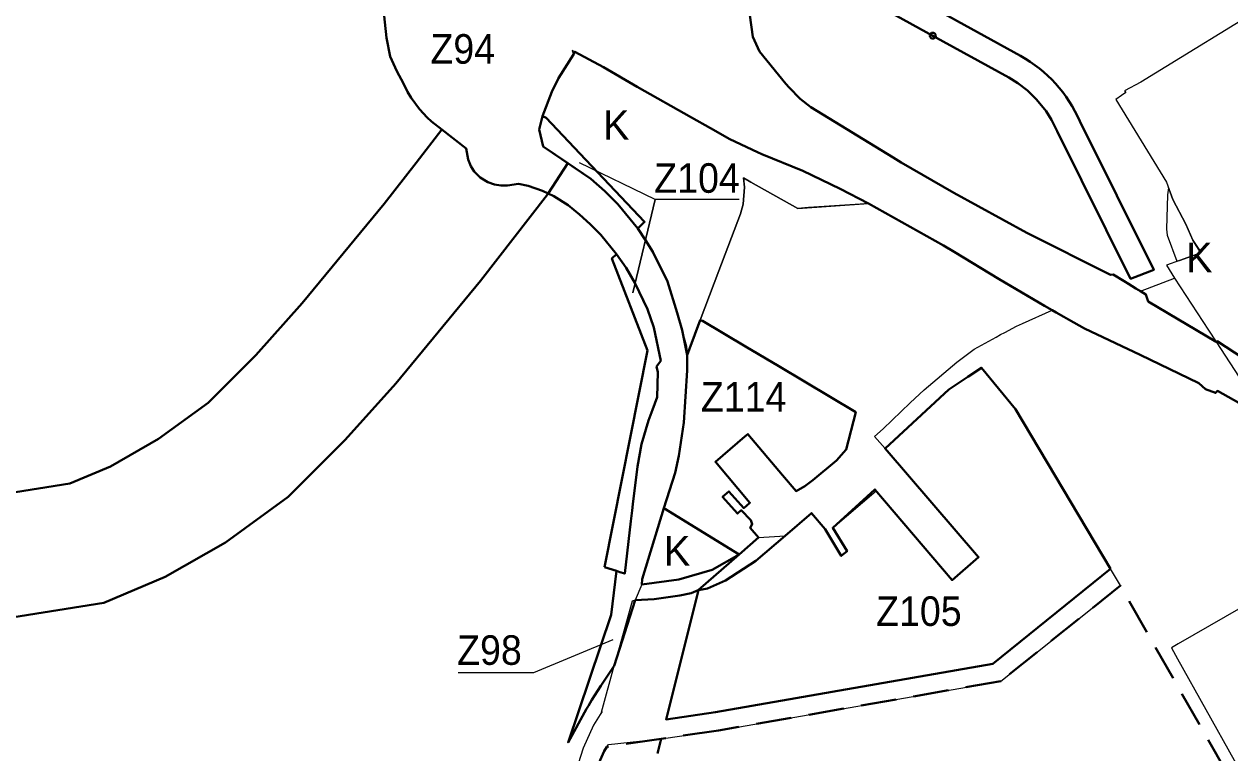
# Model space of a CAD drawing. Extents: x -650276 to -642489, y -1074425 to -1066658.
# Drawn here: x -647044 to -646064, y -1069196 to -1068604 of the extents above; entities that cross this region are included whole.
import ezdxf

# ---------------------------------------------------------------- set-up
doc = ezdxf.new("R2010")
doc.units = 0
doc.header["$LTSCALE"] = 9.6
doc.header["$PDMODE"] = 32
doc.header["$PDSIZE"] = 4.8
doc.linetypes.add('MEDIUM_DASHED', pattern=[4.5, 3, -1.5])
for name, color, linetype, lineweight in [('1', 7, 'Continuous', 13), ('43', 7, 'Continuous', 13), ('44', 7, 'Continuous', 40), ('45', 7, 'Continuous', 40), ('46', 7, 'Continuous', 13), ('47', 7, 'Continuous', 13), ('61', 7, 'MEDIUM_DASHED', 40)]:
    doc.layers.add(name, color=color, linetype=linetype, lineweight=lineweight)

msp = doc.modelspace()

# ---------------------------------------------------------------- linework, layer by layer
at = {"layer": '1'}
for points in [[(-646028.19, -1068584.65), (-646136.66, -1068651.17), (-646149.99, -1068658.12), (-646149.04, -1068659.6), (-646152.41, -1068662.01), (-646157.02, -1068665.31), (-646115.89, -1068732.3), (-646110.72, -1068746.41), (-646100.168, -1068766.374), (-646094.58, -1068779.42), (-646089.04, -1068787.68), (-646088.06, -1068789.6), (-646105.32, -1068795.84), (-646115.95, -1068799.69), (-646109.35, -1068810.23), (-646081.72, -1068852.51), (-646075.56, -1068861.95), (-646053.3, -1068896.01)], [(-646208.7, -1068836.39), (-646214.92, -1068832.85), (-646251.73, -1068811.04), (-646288.37, -1068789.04), (-646357.87, -1068749.64), (-646364.77, -1068750.16), (-646406.7, -1068753.03), (-646415.3, -1068753.62), (-646453.51, -1068732.3), (-646459.54, -1068728.94), (-646458.57, -1068736.31), (-646459.59, -1068750.19), (-646461.92, -1068757.93), (-646479.45, -1068804.37), (-646494.52, -1068844.29), (-646492.73, -1068845.01), (-646457.86, -1068865.8), (-646430.86, -1068881.89), (-646368.3, -1068919.19)], [(-646114.15, -1068737.05), (-646115.07, -1068742.74), (-646115.86, -1068770.5), (-646115.26, -1068775.39), (-646107.5, -1068796.63)], [(-646088.06, -1068789.6), (-646094.58, -1068779.42), (-646100.171, -1068766.368), (-646110.72, -1068746.41), (-646114.013, -1068737.422), (-646114.15, -1068737.05)], [(-646107.5, -1068796.63), (-646105.32, -1068795.84), (-646088.06, -1068789.6)], [(-646368.3, -1068919.19), (-646376.02, -1068949.34), (-646383.86, -1068958.24), (-646403.13, -1068974.41), (-646409.67, -1068979.3), (-646416.71, -1068983.21), (-646427.77, -1068970.39), (-646455.78, -1068936.87), (-646468.83, -1068948.26), (-646482.2, -1068959.52), (-646454.21, -1068992.73), (-646459.25, -1068996.98), (-646471.24, -1068983.41), (-646476.35, -1068987.98), (-646464.24, -1069001.49), (-646461.29, -1068998.81), (-646453.48, -1069006.75), (-646452.37, -1069010.01), (-646453.88, -1069013.1), (-646449.47, -1069018.25), (-646447.2, -1069020.9), (-646425.52, -1069019.41), (-646410.96, -1069006.99), (-646404.269, -1069001.033), (-646393.09, -1069014.234), (-646379.973, -1069035.889), (-646375.346, -1069032.07), (-646386.936, -1069012.936), (-646351.641, -1068983.083), (-646305.65, -1069037.39), (-646290.099, -1069055.423), (-646268.528, -1069036.82), (-646344.49, -1068948.736), (-646353.114, -1068938.868), (-646345.87, -1068932.56), (-646324.04, -1068911.62), (-646312.72, -1068901.07), (-646286.22, -1068878.44), (-646272.13, -1068867.84), (-646254.36, -1068858.21), (-646250.58, -1068856.16), (-646247.14, -1068854.3), (-646237.82, -1068849.24), (-646232.81, -1068847.24), (-646208.7, -1068836.39)], [(-645993.85, -1069042.59), (-646106.31, -1069107.25), (-646111.84, -1069110.389), (-646107, -1069119.41), (-646037.99, -1069242.88)]]:
    msp.add_lwpolyline(points, dxfattribs=at)
at = {"layer": '44'}
for points in [[(-646561.544, -1068464.842), (-646553.677, -1068472.283), (-646544.525, -1068479.79), (-646535.245, -1068486.342), (-646523.105, -1068493.54), (-646493.511, -1068509.855), (-646305.678, -1068613.404)], [(-646234.342, -1068629.893), (-646234.342, -1068629.892), (-646438.626, -1068517.274), (-646513.45, -1068476.025), (-646513.567, -1068475.963)], [(-646337.93, -1068712.4), (-646404.83, -1068671.52), (-646413.45, -1068664.71), (-646422.32, -1068655.58), (-646425.11, -1068652.37), (-646446.54, -1068626.14), (-646451.82, -1068614.31), (-646458.03, -1068569.26), (-646461.14, -1068556.34), (-646469.51, -1068538.15), (-646477.41, -1068526.45), (-646487.92, -1068516.87), (-646498.48, -1068511.26), (-646507.4, -1068508.45), (-646514.39, -1068507.56), (-646528.18, -1068507.58), (-646531.9, -1068509.25), (-646537.71, -1068508.16), (-646545.57, -1068511.42)], [(-646752.59, -1068584.55), (-646749.35, -1068615.18), (-646746.32, -1068630.23), (-646740.91, -1068642.34), (-646735.62, -1068652.21), (-646732.25, -1068659.06), (-646729.34, -1068663.94), (-646722.6, -1068673.11), (-646716.39, -1068679.8), (-646716.39, -1068679.8), (-646712.93, -1068683), (-646704.316, -1068689.698), (-646684.7, -1068704.95), (-646682.98, -1068714.07), (-646680.88, -1068719.28), (-646678.08, -1068723.7)], [(-646305.678, -1068613.404), (-646243.997, -1068647.407), (-646236.707, -1068651.891), (-646228.691, -1068658.051), (-646221.348, -1068665.144), (-646213.659, -1068674.696), (-646209.179, -1068681.795), (-646204.654, -1068690.937), (-646145.083, -1068810.83), (-646126.317, -1068803.654), (-646186.371, -1068682.825)], [(-646602.095, -1068716.98), (-646622.01, -1068703.3), (-646625.35, -1068689.7), (-646622.68, -1068678.75), (-646615.19, -1068659.11), (-646609.7, -1068647.84), (-646597.4, -1068628.74), (-646596.28, -1068626.52), (-646596.28, -1068626.52), (-646573.14, -1068638.98), (-646545.73, -1068654.81), (-646545.73, -1068654.81), (-646501.64, -1068679.81), (-646486.23, -1068688.54), (-646470.65, -1068697.38), (-646448.02, -1068707.99), (-646444.51, -1068709.64), (-646411.3, -1068723.11), (-646380.94, -1068737.81), (-646357.87, -1068749.64), (-646297.08, -1068783.8), (-646288.37, -1068789.04), (-646251.73, -1068811.04), (-646214.92, -1068832.85), (-646208.7, -1068836.39), (-646205.48, -1068838.23), (-646199.24, -1068841.79), (-646195.52, -1068843.92), (-646182.57, -1068851.3), (-646137.23, -1068872.6), (-646089.63, -1068895.5), (-646084.1, -1068900.51), (-646076.09, -1068903.48), (-646074.51, -1068901.9), (-646057.13, -1068911.62)], [(-646704.316, -1068689.698), (-646725.374, -1068716.786), (-646751.116, -1068749.975), (-646817.718, -1068830.545), (-646855.506, -1068872.883), (-646894.206, -1068911.595), (-646934.465, -1068940.759)], [(-646617.991, -1068741.504), (-646622.62, -1068739.32), (-646634.37, -1068735.27), (-646642.04, -1068733.74), (-646651.21, -1068734.99), (-646656.47, -1068735.13), (-646661.5, -1068734.35), (-646667.17, -1068732.38), (-646673.16, -1068728.69), (-646678.08, -1068723.7), (-646680.88, -1068719.28), (-646682.98, -1068714.07), (-646684.7, -1068704.95), (-646704.316, -1068689.698)], [(-646618.655, -1068742.359), (-646617.991, -1068741.504), (-646617.991, -1068741.503), (-646602.095, -1068716.98)], [(-646539.08, -1068779.481), (-646545.32, -1068769.89), (-646561.5, -1068750.22), (-646571.91, -1068739.54), (-646583.49, -1068729.76), (-646602.095, -1068716.98), (-646617.991, -1068741.503)], [(-646046.48, -1068879.92), (-646074.78, -1068861.51), (-646075.56, -1068861.95), (-646130.68, -1068829.21), (-646132.62, -1068823.54), (-646136.99, -1068820.88), (-646140.73, -1068818.61), (-646146.85, -1068814.88), (-646150.26, -1068812.81), (-646159.1, -1068807.43), (-646161.45, -1068807.54), (-646229.44, -1068773.53), (-646288.59, -1068740.88), (-646331.26, -1068716.25), (-646337.93, -1068712.4)], [(-647065.688, -1069087.73), (-646978.92, -1069073.93), (-646929.186, -1069052.925), (-646880.163, -1069024.903), (-646829.104, -1068987.917), (-646782.784, -1068941.581), (-646741.85, -1068895.719), (-646673.05, -1068812.491), (-646618.655, -1068742.359), (-646617.991, -1068741.504)], [(-646617.991, -1068741.503), (-646613.44, -1068743.65), (-646601.86, -1068751.01), (-646592.53, -1068758.66), (-646583.98, -1068766.42), (-646575.28, -1068775.04), (-646562.49, -1068790.69), (-646554.8, -1068801.98)], [(-646509.323, -1068852.529), (-646513.27, -1068838.37), (-646521.18, -1068812.95), (-646532.92, -1068788.95), (-646539.08, -1068779.481)], [(-646554.8, -1068801.98), (-646547.68, -1068814.22), (-646547.433, -1068814.73)], [(-646547.433, -1068814.73), (-646537.35, -1068835.56), (-646532.16, -1068850.47), (-646526.64, -1068877.47), (-646530.06, -1068882.16)], [(-646524, -1068997), (-646514.91, -1068968.48), (-646514.91, -1068968.48), (-646512.07, -1068954.68), (-646507.91, -1068927.47), (-646505.12, -1068885.31), (-646505.17, -1068872.78), (-646509.323, -1068852.529)], [(-646530.06, -1068882.16), (-646528.92, -1068886.55), (-646529.44, -1068906.81), (-646533.28, -1068917.17)], [(-646533.28, -1068917.17), (-646536.54, -1068925.95), (-646542.16, -1068945.12), (-646545.42, -1068963.3), (-646549.17, -1068993.71), (-646549.81, -1068998.88), (-646550.89, -1069007.7), (-646555.84, -1069050.22), (-646559.8, -1069048.98), (-646562.61, -1069048.08)], [(-646934.465, -1068940.759), (-646973.61, -1068963.135), (-647006.63, -1068977.08), (-647076.422, -1068988.18), (-647128.674, -1068991.167), (-647199.672, -1068994.255), (-647268.348, -1068994.255), (-647338.816, -1068991.19), (-647417.895, -1068984.986), (-647502.412, -1068977.157), (-647629.424, -1068964.608), (-647699.561, -1068956.635), (-647749.978, -1068953.416)], [(-646462.98, -1069034.61), (-646485, -1069047), (-646512, -1069055), (-646542, -1069059), (-646541.71, -1069054.76), (-646524, -1068997)], [(-646547.412, -1069071.71), (-646532, -1069071), (-646511, -1069068), (-646502, -1069066), (-646496.317, -1069063.61), (-646462.98, -1069034.61)], [(-646562.61, -1069048.08), (-646566.82, -1069083.62), (-646601.82, -1069187.25), (-646586.97, -1069160.06), (-646585.42, -1069157.56), (-646583.89, -1069155.1), (-646582.46, -1069152.81), (-646582.46, -1069152.81), (-646575.4, -1069141.46), (-646564.54, -1069125.08), (-646547.412, -1069071.71)]]:
    msp.add_lwpolyline(points, dxfattribs=at)
at = {"layer": '44', "lineweight": 13}
msp.add_lwpolyline([(-646691.216, -1069130.395), (-646629.734, -1069130.395), (-646565.156, -1069103.837)], dxfattribs=at)
msp.add_lwpolyline([(-646691.216, -1069130.395), (-646629.734, -1069130.395), (-646565.156, -1069103.837)], dxfattribs=at)
at = {"layer": '44'}
msp.add_arc((-646287.447, -1068726.224), 110, 23.23727, 61.13296, dxfattribs=at)
msp.add_point((-646305.678, -1068613.404), dxfattribs=at)
at = {"layer": '45'}
msp.add_line((-646583.49, -1068729.76), (-646571.91, -1068739.54), dxfattribs=at)
msp.add_line((-646583.49, -1068729.76), (-646571.91, -1068739.54), dxfattribs=at)
for points in [[(-646571.91, -1068739.54), (-646561.5, -1068750.22), (-646545.32, -1068769.89), (-646539.78, -1068764.65), (-646596.93, -1068704.15), (-646619.74, -1068680.15), (-646622.68, -1068678.75), (-646625.35, -1068689.7)], [(-646571.91, -1068739.54), (-646561.5, -1068750.22), (-646545.32, -1068769.89), (-646539.78, -1068764.65), (-646596.93, -1068704.15), (-646619.74, -1068680.15), (-646622.68, -1068678.75), (-646625.35, -1068689.7)], [(-646625.35, -1068689.7), (-646622.01, -1068703.3), (-646583.49, -1068729.76)], [(-646625.35, -1068689.7), (-646622.01, -1068703.3), (-646583.49, -1068729.76)], [(-646562.49, -1068790.69), (-646566.34, -1068794.32), (-646537.3, -1068868.95), (-646572.42, -1069044.94)], [(-646562.49, -1068790.69), (-646566.34, -1068794.32), (-646537.3, -1068868.95), (-646572.42, -1069044.94)], [(-646526.64, -1068877.47), (-646532.16, -1068850.47), (-646537.35, -1068835.56), (-646547.68, -1068814.22), (-646554.8, -1068801.98), (-646562.49, -1068790.69)], [(-646526.64, -1068877.47), (-646532.16, -1068850.47), (-646537.35, -1068835.56), (-646547.68, -1068814.22), (-646554.8, -1068801.98), (-646562.49, -1068790.69)], [(-646529.44, -1068906.81), (-646528.92, -1068886.55), (-646530.06, -1068882.16), (-646526.64, -1068877.47)], [(-646529.44, -1068906.81), (-646528.92, -1068886.55), (-646530.06, -1068882.16), (-646526.64, -1068877.47)], [(-646555.84, -1069050.22), (-646550.89, -1069007.7), (-646549.81, -1068998.88), (-646549.17, -1068993.71), (-646545.42, -1068963.3), (-646542.16, -1068945.12), (-646536.54, -1068925.95), (-646533.28, -1068917.17), (-646529.44, -1068906.81)], [(-646555.84, -1069050.22), (-646550.89, -1069007.7), (-646549.81, -1068998.88), (-646549.17, -1068993.71), (-646545.42, -1068963.3), (-646542.16, -1068945.12), (-646536.54, -1068925.95), (-646533.28, -1068917.17), (-646529.44, -1068906.81)], [(-646572.42, -1069044.94), (-646562.61, -1069048.08), (-646559.8, -1069048.98), (-646555.84, -1069050.22)], [(-646572.42, -1069044.94), (-646562.61, -1069048.08), (-646559.8, -1069048.98), (-646555.84, -1069050.22)]]:
    msp.add_lwpolyline(points, dxfattribs=at)
for points in [[(-646512.07, -1068954.68), (-646507.91, -1068927.47), (-646505.12, -1068885.31), (-646505.17, -1068872.78), (-646503.24, -1068867.61), (-646494.52, -1068844.29), (-646492.73, -1068845.01), (-646457.86, -1068865.8), (-646430.86, -1068881.89), (-646368.3, -1068919.19), (-646376.02, -1068949.34), (-646383.86, -1068958.24), (-646403.13, -1068974.41), (-646409.67, -1068979.3), (-646416.71, -1068983.21), (-646427.77, -1068970.39), (-646455.78, -1068936.87), (-646458.21, -1068938.99), (-646482.2, -1068959.52), (-646454.21, -1068992.73), (-646459.25, -1068996.98), (-646471.24, -1068983.41), (-646476.35, -1068987.98), (-646464.24, -1069001.49), (-646461.29, -1068998.81), (-646453.48, -1069006.75), (-646452.37, -1069010.01), (-646453.88, -1069013.1), (-646447.2, -1069020.9), (-646462.98, -1069034.61), (-646524, -1068997), (-646514.91, -1068968.48), (-646514.91, -1068968.48)], [(-646512.07, -1068954.68), (-646507.91, -1068927.47), (-646505.12, -1068885.31), (-646505.17, -1068872.78), (-646503.24, -1068867.61), (-646494.52, -1068844.29), (-646492.73, -1068845.01), (-646457.86, -1068865.8), (-646430.86, -1068881.89), (-646368.3, -1068919.19), (-646376.02, -1068949.34), (-646383.86, -1068958.24), (-646403.13, -1068974.41), (-646409.67, -1068979.3), (-646416.71, -1068983.21), (-646427.77, -1068970.39), (-646455.78, -1068936.87), (-646458.21, -1068938.99), (-646482.2, -1068959.52), (-646454.21, -1068992.73), (-646459.25, -1068996.98), (-646471.24, -1068983.41), (-646476.35, -1068987.98), (-646464.24, -1069001.49), (-646461.29, -1068998.81), (-646453.48, -1069006.75), (-646452.37, -1069010.01), (-646453.88, -1069013.1), (-646447.2, -1069020.9), (-646462.98, -1069034.61), (-646524, -1068997), (-646514.91, -1068968.48), (-646514.91, -1068968.48)], [(-646161.484, -1069046.228), (-646238.632, -1068916.799), (-646266.118, -1068883.048), (-646277.268, -1068890.446), (-646292.75, -1068900.72), (-646344.49, -1068948.736), (-646268.528, -1069036.82), (-646290.099, -1069055.423), (-646352.71, -1068981.82), (-646386.936, -1069012.936), (-646375.346, -1069032.07), (-646379.973, -1069035.889), (-646393.09, -1069014.234), (-646404.269, -1069001.033), (-646425.52, -1069019.41), (-646449.418, -1069039.804), (-646474.13, -1069055.83), (-646488.537, -1069062.169), (-646495.89, -1069063.531), (-646522.35, -1069168.648), (-646482.211, -1069162.813), (-646256.824, -1069123.414)], [(-646161.484, -1069046.228), (-646238.632, -1068916.799), (-646266.118, -1068883.048), (-646277.268, -1068890.446), (-646292.75, -1068900.72), (-646344.49, -1068948.736), (-646268.528, -1069036.82), (-646290.099, -1069055.423), (-646352.71, -1068981.82), (-646386.936, -1069012.936), (-646375.346, -1069032.07), (-646379.973, -1069035.889), (-646393.09, -1069014.234), (-646404.269, -1069001.033), (-646425.52, -1069019.41), (-646449.418, -1069039.804), (-646474.13, -1069055.83), (-646488.537, -1069062.169), (-646495.89, -1069063.531), (-646522.35, -1069168.648), (-646482.211, -1069162.813), (-646256.824, -1069123.414)]]:
    msp.add_lwpolyline(points, close=True, dxfattribs=at)
at = {"layer": '46'}
msp.add_lwpolyline([(-646462.83, -1068746.366), (-646531.233, -1068746.366), (-646549.233, -1068822.328), (-646531.233, -1068746.366), (-646592.58, -1068716.54)], dxfattribs=at)
msp.add_lwpolyline([(-646462.83, -1068746.366), (-646531.233, -1068746.366), (-646549.233, -1068822.328), (-646531.233, -1068746.366), (-646592.58, -1068716.54)], dxfattribs=at)
at = {"layer": '47'}
msp.add_line((-646462.98, -1069034.61), (-646524, -1068997), dxfattribs=at)
msp.add_lwpolyline([(-646513.27, -1068838.37), (-646505.69, -1068865.56), (-646505.17, -1068872.78), (-646503.24, -1068867.61), (-646494.52, -1068844.29), (-646479.45, -1068804.37), (-646461.92, -1068757.93), (-646459.59, -1068750.19), (-646458.57, -1068736.31), (-646459.54, -1068728.94), (-646453.51, -1068732.3), (-646415.3, -1068753.62), (-646357.87, -1068749.64), (-646411.3, -1068723.11), (-646448.02, -1068707.99), (-646470.65, -1068697.38), (-646486.23, -1068688.54), (-646501.64, -1068679.81), (-646545.73, -1068654.81), (-646573.14, -1068638.98), (-646598.59, -1068625.34), (-646597.4, -1068628.74), (-646609.7, -1068647.84), (-646615.19, -1068659.11), (-646622.68, -1068678.75), (-646619.74, -1068680.15), (-646596.93, -1068704.15), (-646539.78, -1068764.65), (-646545.32, -1068769.89), (-646532.92, -1068788.95), (-646521.18, -1068812.95)], close=True, dxfattribs=at)
for points in [[(-646075.56, -1068861.95), (-646130.68, -1068829.21), (-646132.62, -1068823.54), (-646136.99, -1068820.88), (-646109.35, -1068810.23)], [(-646109.35, -1068810.23), (-646081.72, -1068852.51), (-646075.56, -1068861.95)], [(-646524, -1068997), (-646541.71, -1069054.76), (-646542, -1069059), (-646547.412, -1069071.71)], [(-646495.89, -1069063.531), (-646496.317, -1069063.61), (-646496.317, -1069063.61), (-646462.98, -1069034.61)], [(-646593.793, -1069255.911), (-646577.878, -1069206.485), (-646572.586, -1069194.485), (-646569.114, -1069188.86), (-646526.31, -1069184.381), (-646479.84, -1069177.626), (-646250.409, -1069137.52), (-646153.307, -1069059.947), (-646161.484, -1069046.228), (-646256.824, -1069123.414)], [(-646256.824, -1069123.414), (-646482.211, -1069162.813), (-646522.35, -1069168.648), (-646495.89, -1069063.531)], [(-646547.412, -1069071.71), (-646549.91, -1069072.542), (-646564.54, -1069125.08), (-646564.605, -1069125.271), (-646574.978, -1069163.017), (-646574.978, -1069163.017), (-646574.33, -1069162.04), (-646575.87, -1069164.54), (-646581.29, -1069173.32), (-646589.56, -1069192.07), (-646601.41, -1069229.34)]]:
    msp.add_lwpolyline(points, dxfattribs=at)
at = {"layer": '61'}
for points in [[(-646583.457, -1069759.191), (-646554.262, -1069762.602), (-646321.973, -1069686.855), (-646209.9, -1069538.5), (-646146.8, -1069506.6), (-646148.5, -1069503), (-646028.16, -1069441.58), (-646023.96, -1069440.34), (-646075.49, -1069318.19), (-646025.14, -1069285.394), (-646153.307, -1069059.947)], [(-646153.307, -1069059.947), (-646250.409, -1069137.52), (-646479.84, -1069177.626), (-646526.31, -1069184.381)]]:
    msp.add_lwpolyline(points, dxfattribs=at)
msp.add_lwpolyline([(-646572.586, -1069194.485), (-646577.878, -1069206.485), (-646611.107, -1069309.68), (-646626.774, -1069359.349), (-646580.797, -1069364.111), (-646571.479, -1069363.822), (-646526.31, -1069184.381), (-646570.296, -1069190.776)], close=True, dxfattribs=at)

# ---------------------------------------------------------------- texts
at = {"layer": '43'}
for p in [(-646573.463, -1068697.908), (-646573.463, -1068697.908), (-646099.972, -1068805.526), (-646524.065, -1069043.743), (-646524.065, -1069043.743)]:
    msp.add_text('K', height=24, dxfattribs=at).set_placement(p)
at = {"layer": '44', "width": 0.95}
for s, p in [('Z94', (-646713.687, -1068636.144)), ('Z94', (-646713.687, -1068636.144)), ('Z98', (-646691.993, -1069124.279)), ('Z98', (-646691.993, -1069124.279))]:
    msp.add_text(s, height=24, dxfattribs=at).set_placement(p)
at = {"layer": '46', "width": 0.95}
for s, p in [('Z104', (-646531.893, -1068740.983)), ('Z104', (-646531.893, -1068740.983)), ('Z114', (-646493.997, -1068918.587)), ('Z114', (-646493.997, -1068918.587)), ('Z105', (-646351.762, -1069092.692)), ('Z105', (-646351.762, -1069092.692))]:
    msp.add_text(s, height=24, dxfattribs=at).set_placement(p)

doc.saveas('drawing.dxf')
